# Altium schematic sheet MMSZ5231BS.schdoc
size 127 x 101 mm
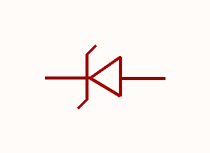
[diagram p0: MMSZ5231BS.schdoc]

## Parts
D?  mmsz5231bs  [SOD-323_L1.7-W1.3-LS2.7-RD]  (value not drawn)

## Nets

Not connected (* = marked no-connect by the designer): D? 1(K) 2(A)

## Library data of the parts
D? = mmsz5231bs: 二极管配置:1个独立式;稳压值(标称值):5.1V;稳压值(范围值):4.85V~5.36V;耗散功率(Pd):200mW;; Manufacturer: CJ(江苏长电/长晶); AddInBom: yes; ModelId: cb3f162a5497409a8a6cf33769e88f04; ModelTransform: 102.362,50.197,0,0,0,0,0,0,0; Diode Configuration: 1个独立式; Zener Voltage(Nom): 5.1V; Reverse Leakage Current (Ir): 5uA; Pd - Power Dissipation: 200mW; Impedance(Zzt): 17Ω; Impedance(Zzk): 1.6kΩ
